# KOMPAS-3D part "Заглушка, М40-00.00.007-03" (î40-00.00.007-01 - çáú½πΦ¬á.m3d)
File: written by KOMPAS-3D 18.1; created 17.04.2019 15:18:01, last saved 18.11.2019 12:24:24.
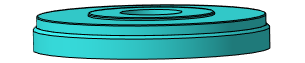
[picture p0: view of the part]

Document properties: Автор: kon; Организация: Elma; Полное имя файла: D:\Magna\Магна Ins\Магна ins 40\3Д\М40-00.00.007-01 - Заглушка.m3d

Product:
- Part/product: Заглушка  | designation М40-00.00.007-03
    Масса: 8.03373
    source file: М40-00.00.007 - Заглушка.cdw
- Part/product: Заглушка  | designation М40-00.00.007-02
    Масса: 8.60848
- Part/product: Деталь  | designation М40-00.00.007
    Масса: 7.02731
- Part/product: Заглушка  | designation М40-00.00.007-01
    Масса: 9.35455
- Part/product: Заглушка  | designation М32-00.00.007М32
    Масса: 8.94851
    source file: ..\..\Магна ins 32\М32-00.00.007 - Заглушка.cdw
- Part/product: Заглушка ПВХ  | designation М40-10.00.007-ПВХ
    Масса: 4.70059
- Part/product: Косячная (удолить)  | designation М40-00.00.007-6666
    Масса: 8.81523
    source file: М40-00.00.007-06 - Заглушка.cdw

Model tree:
1. Эскиз:1
2. Операция вращения:1  (labels: v10_v865; v10_v471)
     Угол 1 = 360
3. Скругление:1  (with: Операция вращения:1)
     Радиус = 4
4. Эскиз:2  (with: Операция вращения:1)
5. Отверстие:1  (with: Операция вращения:1)
     Глубина выреза = 10; Диаметр отверстия = 8; Угол конуса торца = 118; Расстояние 1 = 65
6. Массив по концентрической сетке:1  (with: Отверстие:1, Эскиз:2)  (4 pattern instances)
     Шаг 2 = 360
7. Скругление:2  (with: Операция вращения:1)
     Радиус = 10
8. Фаска:7  (with: Операция вращения:1)
     Угол = 45; Длина 1 = 1; Длина 2 = 1
9. Условное изображение резьбы:6  (with: Операция вращения:1, Фаска:7)  (labels: M225x4; cil0_24705-2004 fine)
     Длина резьбы = 20; Шаг резьбы = 4; Номинальный диаметр резьбы = 225
10. Подгонка:1  (with: Операция вращения:1)
11. Фаска:8  (with: Операция вращения:1)
     Угол = 45; Длина 1 = 3; Длина 2 = 3
12. Фаска:14  (with: Операция вращения:1)  (labels: v10_v465)
     Угол = 45; Длина 1 = 1; Длина 2 = 1
13. Условное изображение резьбы:5  (with: Операция вращения:1)  (labels: M225x4; cil0_24705-2004 fine)
     Длина резьбы = 25; Шаг резьбы = 4; Номинальный диаметр резьбы = 225
14. Подгонка:4  (with: Операция вращения:1)
15. Эскиз:3  (with: Операция вращения:1)
16. Вырезать элемент выдавливания:1
     Расстояние 1 = 10
17. Фаска:4  (with: Вырезать элемент выдавливания:1)
     Угол = 45; Длина 1 = 4; Длина 2 = 4
18. Операция выдавливания:1  (with: Операция вращения:1)
     Расстояние 1 = 4
19. Вырезать элемент выдавливания:2  (with: Операция вращения:1, Операция выдавливания:1)
     Расстояние 1 = 4.5
20. Эскиз:5  (with: Операция выдавливания:1, Вырезать элемент выдавливания:2)
21. Операция выдавливания:2
     Расстояние 1 = 7.5
22. Вырезать элемент выдавливания:3  (with: Операция выдавливания:2)
     Расстояние 1 = 7.5
23. Вырезать элемент выдавливания:5  (with: Операция выдавливания:1)
     Расстояние 1 = 9
24. Вырезать элемент выдавливания:6  (with: Операция выдавливания:2)
     Расстояние 1 = 9
25. Фаска:6  (with: Вырезать элемент выдавливания:5)
     Угол = 45; Длина 1 = 1; Длина 2 = 1
26. Фаска:13  (with: Вырезать элемент выдавливания:6)  (labels: v10_v865; v10_v471; v10_v465)
     Угол = 45; Длина 1 = 1; Длина 2 = 1
27. Условное изображение резьбы:11  (with: Операция вращения:1)  (labels: M155x4; cil0_24705-2004 fine)
     Длина резьбы = 32; Шаг резьбы = 4; Номинальный диаметр резьбы = 155
28. Подгонка:2  (with: Операция вращения:1)
29. Фаска:11  (with: Операция вращения:1)  (labels: М40-00.00.007-02 - Заглушка с трубой 90.a3d)
     Угол = 45; Длина 1 = 2.5; Длина 2 = 2.5
30. Эскиз:11  (with: Операция вращения:1, Элемент выдавливания:1)  (labels: Труба 90*15 PN20)
31. Элемент выдавливания:2
     Расстояние 2 = 10.5
32. Скругление:3  (with: Элемент выдавливания:2)
     Радиус = 4
33. Условное изображение резьбы:12  (with: Операция вращения:1, Элемент выдавливания:2)  (labels: M90x3; cil0_24705-2004 fine)
     Длина резьбы = 26; Шаг резьбы = 3; Номинальный диаметр резьбы = 90
34. Подгонка:1  (with: Операция вращения:1)
35. Фаска:12  (with: Операция вращения:1)
     Угол = 45; Длина 1 = 2.5; Длина 2 = 2.5
36. Эскиз:13  (with: Элемент выдавливания:2)
37. Элемент выдавливания:4  (labels: v10_v865; v10_v471; v10_v465)
     Расстояние 1 = 4
38. Эскиз:15  (with: Операция вращения:1, Элемент выдавливания:1)  (labels: Всасывающая труба полипропилен 110 PN16)
39. Элемент выдавливания:5
     Расстояние 2 = 25
40. Фаска:15  (with: Элемент выдавливания:5)  (labels: v10_v865; v10_v471; v10_v465)
     Угол = 45; Длина 1 = 3; Длина 2 = 3
41. Эскиз:16  (with: Операция вращения:1, Фаска:14)
42. Элемент выдавливания:6  (with: Операция вращения:1)
43. Эскиз:18  (with: Операция вращения:1, Элемент выдавливания:6)
44. Элемент выдавливания:8
     Расстояние 1 = 6
45. Эскиз:19  (with: Элемент выдавливания:8)
46. Элемент выдавливания:9  (with: Операция вращения:1)
     Расстояние 2 = 2.5
47. Фаска:19  (with: Элемент выдавливания:9)
     Угол = 45; Длина 1 = 1; Длина 2 = 1

Referenced files in D:\Magna\Магна Ins\Магна ins 40\3Д\: М40-00.00.007-02 - Заглушка с трубой 90.a3d, М40-00.00.007-01 - Заглушка.a3d

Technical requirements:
  Gost Type A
